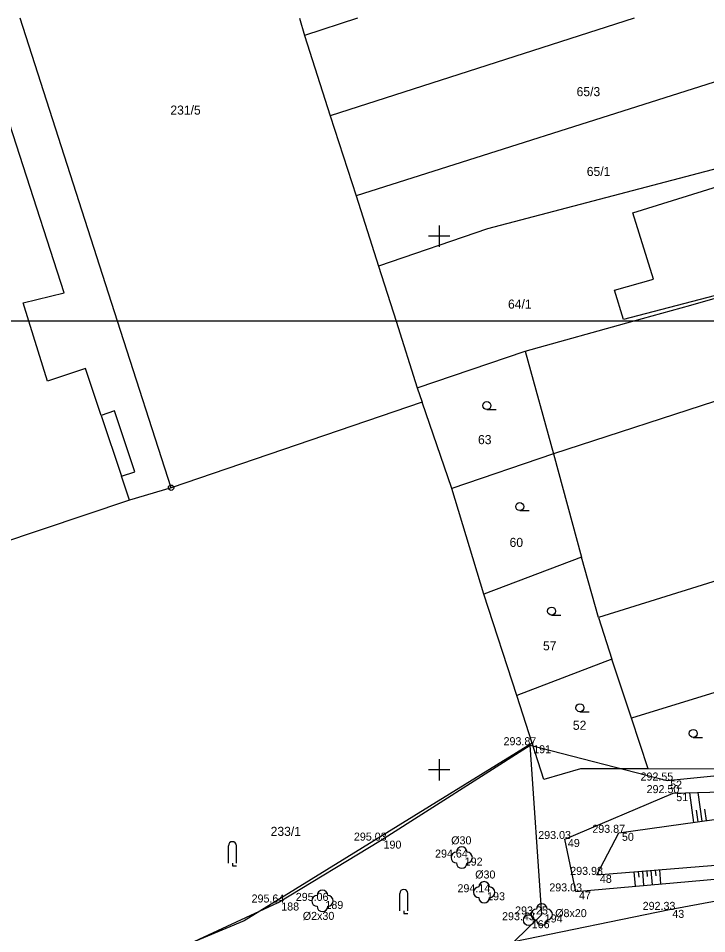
# Model space of a CAD drawing. Extents: x -599866 to -590076, y -1178039 to -1154526.
# Drawn here: x -599789.5 to -599724.9, y -1154615.4 to -1154529.6 of the extents above; entities that cross this region are included whole.
import ezdxf

# ---------------------------------------------------------------- set-up
doc = ezdxf.new("R2010")
doc.units = 0
for name, color, linetype in [('IS neurčené', 7, 'Continuous'), ('KN', 7, 'Continuous'), ('Ploty', 7, 'Continuous'), ('Popisy', 7, 'Continuous'), ('Rozhraní ploch', 7, 'Continuous'), ('Rám', 7, 'Continuous'), ('Vegetace', 7, 'Continuous'), ('Vrstva 5', 7, 'Continuous'), ('Vrstva 58', 7, 'Continuous'), ('Vrstva 59', 7, 'Continuous'), ('Vrstva 60', 7, 'Continuous'), ('Výškopis', 7, 'Continuous'), ('Značky kultur', 7, 'Continuous')]:
    doc.layers.add(name, color=color, linetype=linetype)

msp = doc.modelspace()

# ---------------------------------------------------------------- linework, layer by layer
at = {"layer": 'IS neurčené'}
msp.add_circle((-599741.61, -1154614.09), 0.5, dxfattribs=at)
at = {"layer": 'KN'}
for p, q in [((-599780.163, -1154557.95), (-599789.295, -1154529.575)), ((-599763.102, -1154529.575), (-599762.63, -1154531.18)), ((-599757.661, -1154529.575), (-599762.63, -1154531.18)), ((-599731.738, -1154529.575), (-599760.21, -1154538.7)), ((-599762.63, -1154531.18), (-599760.21, -1154538.7)), ((-599711.61, -1154531.55), (-599757.79, -1154546.22)), ((-599760.21, -1154538.7), (-599757.79, -1154546.22)), ((-599757.79, -1154546.22), (-599755.69, -1154552.79)), ((-599755.69, -1154552.79), (-599754.048, -1154557.95)), ((-599775.14, -1154573.56), (-599780.163, -1154557.95)), ((-599754.048, -1154557.95), (-599752.06, -1154564.2)), ((-599704.76, -1154559.14), (-599739.29, -1154570.4)), ((-599752.06, -1154564.2), (-599741.96, -1154560.76)), ((-599741.96, -1154560.76), (-599739.29, -1154570.4)), ((-599752.06, -1154564.2), (-599751.59, -1154565.56)), ((-599751.59, -1154565.56), (-599775.14, -1154573.56)), ((-599748.83, -1154573.64), (-599751.59, -1154565.56)), ((-599745.537, -1154566.24), (-599744.662, -1154566.24)), ((-599781.69, -1154566.78), (-599779.78, -1154572.49)), ((-599739.29, -1154570.4), (-599748.83, -1154573.64)), ((-599739.29, -1154570.4), (-599736.65, -1154580.06)), ((-599775.14, -1154573.56), (-599779.03, -1154574.73)), ((-599745.81, -1154583.53), (-599748.83, -1154573.64)), ((-599779.03, -1154574.73), (-599806.74, -1154583.989)), ((-599701.39, -1154575.17), (-599735.08, -1154585.73)), ((-599742.456, -1154575.71), (-599741.581, -1154575.71)), ((-599736.65, -1154580.06), (-599745.81, -1154583.53)), ((-599735.08, -1154585.73), (-599736.65, -1154580.06)), ((-599742.74, -1154593.02), (-599745.81, -1154583.53)), ((-599696.79, -1154584.29), (-599731.99, -1154595.15)), ((-599739.466, -1154585.5), (-599738.591, -1154585.5)), ((-599735.08, -1154585.73), (-599733.83, -1154589.64)), ((-599733.83, -1154589.64), (-599742.74, -1154593.02)), ((-599731.99, -1154595.15), (-599733.83, -1154589.64)), ((-599741.29, -1154597.51), (-599742.74, -1154593.02)), ((-599736.816, -1154594.56), (-599735.941, -1154594.56)), ((-599730.43, -1154599.91), (-599731.99, -1154595.15)), ((-599741.29, -1154597.51), (-599768.28, -1154614.14)), ((-599720.86, -1154599.93), (-599730.43, -1154599.91)), ((-599768.28, -1154614.14), (-599782.89, -1154620.22))]:
    msp.add_line(p, q, dxfattribs=at)
for points in [[(-599788.477, -1154557.95), (-599789.01, -1154556.24), (-599785.17, -1154555.3), (-599793.491, -1154529.575)], [(-599709.19, -1154539.72), (-599710.84, -1154540.22), (-599745.47, -1154549.29), (-599755.69, -1154552.79)], [(-599714.88, -1154553.16), (-599732.72, -1154557.8), (-599733.57, -1154555.04), (-599729.92, -1154554.02), (-599731.84, -1154547.79), (-599723.93, -1154545.34), (-599722.65, -1154549.43), (-599707.6, -1154544.72), (-599709.19, -1154539.72)], [(-599731.839, -1154557.95), (-599726.4, -1154556.44), (-599714.88, -1154553.16)], [(-599779.03, -1154574.73), (-599779.78, -1154572.49), (-599778.54, -1154572.08), (-599780.45, -1154566.37), (-599781.69, -1154566.78), (-599783.15, -1154562.4), (-599786.72, -1154563.59), (-599788.477, -1154557.95)], [(-599741.96, -1154560.76), (-599731.839, -1154557.95)], [(-599730.43, -1154599.91), (-599736.76, -1154599.9), (-599740.19, -1154600.9), (-599741.29, -1154597.51)]]:
    msp.add_lwpolyline(points, dxfattribs=at)
for centre, radius in [((-599745.536, -1154565.865), 0.375), ((-599775.14, -1154573.56), 0.25), ((-599775.14, -1154573.56), 0.0152), ((-599742.456, -1154575.335), 0.375), ((-599739.466, -1154585.125), 0.375), ((-599736.816, -1154594.185), 0.375)]:
    msp.add_circle(centre, radius, dxfattribs=at)
at = {"layer": 'Ploty'}
for points in [[(-599773.59, -1154654.72), (-599777.41, -1154633.16), (-599780.31, -1154619.48), (-599765.09, -1154612.43), (-599755.5, -1154606.63), (-599741.47, -1154597.69)], [(-599741.47, -1154597.69), (-599728.63, -1154601), (-599697.49, -1154597.88)]]:
    msp.add_lwpolyline(points, dxfattribs=at)
at = {"layer": 'Rozhraní ploch'}
msp.add_lwpolyline([(-599667.9, -1154612.89), (-599675.04, -1154613.39), (-599685.4, -1154611.07), (-599697.37, -1154608.84), (-599702.27, -1154608.44), (-599710.05, -1154609.5), (-599717.18, -1154611.01), (-599728.43, -1154613.12), (-599743.01, -1154616.13), (-599747.93, -1154617.19), (-599756.51, -1154619.89), (-599759.81, -1154622.38), (-599761.46, -1154625.74), (-599766.76, -1154645.89), (-599769.23, -1154663.03), (-599766.8, -1154663.87)], dxfattribs=at)
at = {"layer": 'Rám'}
msp.add_lwpolyline([(-599701.74, -1154557.95), (-599806.74, -1154557.95)], dxfattribs=at)
at = {"layer": 'Vegetace'}
msp.add_lwpolyline([(-599743.01, -1154616.13), (-599740.39, -1154613.55), (-599741.47, -1154597.69)], dxfattribs=at)
for centre in [(-599747.89, -1154608.22), (-599745.79, -1154611.47), (-599760.95, -1154612.28), (-599740.39, -1154613.55)]:
    msp.add_circle(centre, 0.0005, dxfattribs=at)
for centre, start, end in [((-599748.39, -1154608.22), 89.99999, 269.99999), ((-599747.89, -1154607.72), 0, 179.99999), ((-599747.39, -1154608.22), 270, 89.99999), ((-599747.89, -1154608.72), 179.99999, 359.99999), ((-599746.29, -1154611.47), 89.99999, 269.99999), ((-599745.79, -1154610.97), 0, 179.99999), ((-599745.29, -1154611.47), 270, 89.99999), ((-599761.45, -1154612.28), 89.99999, 269.99999), ((-599760.95, -1154611.78), 0, 179.99999), ((-599760.45, -1154612.28), 270, 89.99999), ((-599745.79, -1154611.97), 179.99999, 359.99999), ((-599760.95, -1154612.78), 179.99999, 359.99999), ((-599740.39, -1154613.05), 0, 179.99999), ((-599740.89, -1154613.55), 89.99999, 269.99999), ((-599739.89, -1154613.55), 270, 89.99999), ((-599740.39, -1154614.05), 179.99999, 359.99999)]:
    msp.add_arc(centre, 0.5, start, end, dxfattribs=at)
at = {"layer": 'Vrstva 5'}
for p, q in [((-599750, -1154549), (-599750, -1154551)), ((-599749, -1154550), (-599751, -1154550)), ((-599750, -1154599), (-599750, -1154601)), ((-599749, -1154600), (-599751, -1154600))]:
    msp.add_line(p, q, dxfattribs=at)
at = {"layer": 'Vrstva 60'}
for p, q in [((-599741.47, -1154597.69), (-599741.47, -1154597.69)), ((-599728.63, -1154601), (-599728.63, -1154601)), ((-599728.06, -1154602.18), (-599728.06, -1154602.18)), ((-599733.15, -1154605.9), (-599733.15, -1154605.9)), ((-599755.5, -1154606.63), (-599755.5, -1154606.63)), ((-599738.22, -1154606.48), (-599738.22, -1154606.48)), ((-599747.89, -1154608.22), (-599747.89, -1154608.22)), ((-599735.22, -1154609.84), (-599735.22, -1154609.84)), ((-599745.79, -1154611.47), (-599745.79, -1154611.47)), ((-599737.18, -1154611.39), (-599737.18, -1154611.39)), ((-599765.09, -1154612.43), (-599765.09, -1154612.43)), ((-599760.95, -1154612.28), (-599760.95, -1154612.28)), ((-599740.39, -1154613.55), (-599740.39, -1154613.55)), ((-599728.43, -1154613.12), (-599728.43, -1154613.12)), ((-599741.61, -1154614.09), (-599741.61, -1154614.09))]:
    msp.add_line(p, q, dxfattribs=at)
at = {"layer": 'Výškopis'}
for p, q in [((-599726.133, -1154604.922), (-599726.521, -1154602.14)), ((-599725.34, -1154604.812), (-599725.716, -1154602.119)), ((-599725.737, -1154604.867), (-599725.889, -1154603.772)), ((-599724.944, -1154604.757), (-599725.092, -1154603.697)), ((-599730.947, -1154609.495), (-599730.839, -1154610.829)), ((-599730.548, -1154609.462), (-599730.505, -1154609.995)), ((-599730.15, -1154609.43), (-599730.042, -1154610.759)), ((-599729.751, -1154609.398), (-599729.708, -1154609.928)), ((-599729.352, -1154609.366), (-599729.245, -1154610.689)), ((-599731.744, -1154609.559), (-599731.636, -1154610.9)), ((-599731.346, -1154609.527), (-599731.302, -1154610.062))]:
    msp.add_line(p, q, dxfattribs=at)
for points in [[(-599737.18, -1154611.39), (-599738.22, -1154606.48), (-599728.06, -1154602.18), (-599717.76, -1154601.91), (-599701.19, -1154600.08)], [(-599737.18, -1154611.39), (-599714.33, -1154609.37), (-599699.47, -1154603.6), (-599701.19, -1154600.08)], [(-599735.22, -1154609.84), (-599716.04, -1154608.29), (-599701.19, -1154602.02)], [(-599733.15, -1154605.9), (-599716.86, -1154603.63), (-599701.19, -1154602.02)], [(-599735.22, -1154609.84), (-599733.15, -1154605.9)]]:
    msp.add_lwpolyline(points, dxfattribs=at)
at = {"layer": 'Značky kultur'}
for p, q in [((-599726.19, -1154596.966), (-599725.314, -1154596.966)), ((-599769.766, -1154608.73), (-599769.766, -1154607.106)), ((-599769.014, -1154608.73), (-599769.014, -1154607.106)), ((-599753.696, -1154613.21), (-599753.696, -1154611.586)), ((-599752.944, -1154613.21), (-599752.944, -1154611.586))]:
    msp.add_line(p, q, dxfattribs=at)
for points in [[(-599769.39, -1154608.73), (-599769.39, -1154608.98), (-599769.014, -1154608.98)], [(-599753.32, -1154613.21), (-599753.32, -1154613.46), (-599752.944, -1154613.46)]]:
    msp.add_lwpolyline(points, dxfattribs=at)
msp.add_circle((-599726.19, -1154596.59), 0.375, dxfattribs=at)
for centre in [(-599769.39, -1154607.105), (-599753.32, -1154611.585)]:
    msp.add_arc(centre, 0.375, 0, 179.99999, dxfattribs=at)

# ---------------------------------------------------------------- texts
at = {"layer": 'KN'}
for s, p in [('65/3', (-599737.122, -1154536.87)), ('231/5', (-599775.207, -1154538.6)), ('65/1', (-599736.17, -1154544.35)), ('64/1', (-599743.553, -1154556.78)), ('63', (-599746.366, -1154569.48)), ('60', (-599743.406, -1154579.11)), ('57', (-599740.276, -1154588.8)), ('52', (-599737.473, -1154596.249)), ('233/1', (-599765.807, -1154606.19))]:
    msp.add_text(s, height=0.85, dxfattribs=at).set_placement(p)
at = {"layer": 'Popisy'}
for s, p in [('Ø30', (-599748.88, -1154606.98)), ('Ø30', (-599746.63, -1154610.18)), ('Ø2x30', (-599762.79, -1154614.06)), ('Ø8x20', (-599739.13, -1154613.8))]:
    msp.add_text(s, height=0.75, dxfattribs=at).set_placement(p)
at = {"layer": 'Vrstva 58'}
for s, p in [('293.87 ', (-599743.97, -1154597.69)), ('292.55 ', (-599731.13, -1154601)), ('292.50 ', (-599730.56, -1154602.18)), ('293.87 ', (-599735.65, -1154605.9)), ('295.03 ', (-599758, -1154606.63)), ('293.03 ', (-599740.72, -1154606.48)), ('294.64 ', (-599750.39, -1154608.22)), ('293.98 ', (-599737.72, -1154609.84)), ('294.14 ', (-599748.29, -1154611.47)), ('293.03 ', (-599739.68, -1154611.39)), ('295.64 ', (-599767.59, -1154612.43)), ('295.06 ', (-599763.45, -1154612.28)), ('293.25 ', (-599742.89, -1154613.55)), ('292.33 ', (-599730.93, -1154613.12)), ('293.43 ', (-599744.11, -1154614.09))]:
    msp.add_text(s, height=0.75, dxfattribs=at).set_placement(p)
at = {"layer": 'Vrstva 59'}
for s, p in [(' 191', (-599741.47, -1154598.44)), (' 52', (-599728.63, -1154601.75)), (' 51', (-599728.06, -1154602.93)), (' 50', (-599733.15, -1154606.65)), (' 190', (-599755.5, -1154607.38)), (' 49', (-599738.22, -1154607.23)), (' 192', (-599747.89, -1154608.97)), (' 48', (-599735.22, -1154610.59)), (' 193', (-599745.79, -1154612.22)), (' 47', (-599737.18, -1154612.14)), (' 188', (-599765.09, -1154613.18)), (' 189', (-599760.95, -1154613.03)), (' 194', (-599740.39, -1154614.3)), (' 43', (-599728.43, -1154613.87)), (' 166', (-599741.61, -1154614.84))]:
    msp.add_text(s, height=0.75, dxfattribs=at).set_placement(p)

doc.saveas('drawing.dxf')
